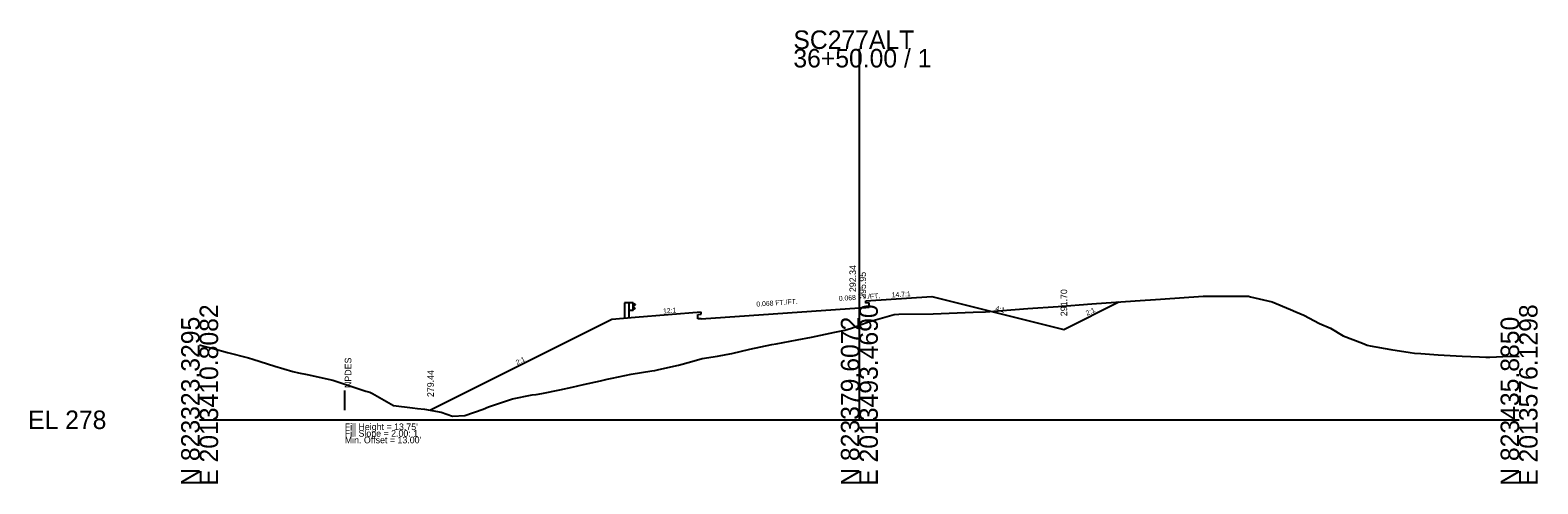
# Model space of a CAD drawing. Extents: x 205929 to 2357175, y -1785700 to 827636.
# Drawn here: x 2018394.5 to 2018623, y 824534.6 to 824603.3 of the extents above; entities that cross this region are included whole.
import ezdxf

# ---------------------------------------------------------------- set-up
doc = ezdxf.new("R2010")
doc.units = 0
for name, color, linetype in [('RD_GPK_XS_Cell', 7, 'Continuous'), ('RD_XS_Base', 7, 'Continuous'), ('RD_XS_EarthShd', 7, 'Continuous'), ('RD_XS_ExGround', 7, 'Continuous'), ('RD_XS_GR', 7, 'Continuous'), ('RD_XS_NPDES', 7, 'Continuous'), ('RD_XS_Pave', 7, 'Continuous'), ('RD_XS_TieSlope', 7, 'Continuous'), ('RD_XS_TX_Elev_EX', 7, 'Continuous'), ('RD_XS_TX_Elev_PR', 7, 'Continuous'), ('RD_XS_TX_ShdSlope', 7, 'Continuous'), ('RD_XS_TX_Slope', 7, 'Continuous'), ('RD_XS_TX_Warning', 7, 'Continuous')]:
    doc.layers.add(name, color=color, linetype=linetype)

msp = doc.modelspace()

# ---------------------------------------------------------------- linework, layer by layer
at = {"layer": 'RD_GPK_XS_Cell'}
for p, q in [((2018520.17, 824544.26), (2018520.17, 824600.42)), ((2018420.17, 824544.26), (2018520.17, 824544.26)), ((2018520.17, 824544.26), (2018620.17, 824544.26))]:
    msp.add_line(p, q, dxfattribs=at)
at = {"layer": 'RD_XS_Base'}
for p, q in [((2018496.17, 824559.57), (2018520.17, 824561.2)), ((2018520.17, 824561.2), (2018521.17, 824561.27))]:
    msp.add_line(p, q, dxfattribs=at)
at = {"layer": 'RD_XS_EarthShd'}
for p, q in [((2018521.17, 824562.27), (2018531.17, 824562.95)), ((2018486.17, 824559.74), (2018482.67, 824559.45)), ((2018496.17, 824560.57), (2018486.17, 824559.74))]:
    msp.add_line(p, q, dxfattribs=at)
at = {"layer": 'RD_XS_ExGround'}
msp.add_lwpolyline([(2018420.17, 824555.59), (2018420.79, 824555.42), (2018422.2, 824555.04), (2018424.38, 824554.45), (2018427.6, 824553.63), (2018428.24, 824553.46), (2018431.58, 824552.37), (2018434.29, 824551.58), (2018435.18, 824551.35), (2018436.49, 824551.11), (2018440.34, 824550.27), (2018445.37, 824548.6), (2018445.98, 824548.42), (2018446.39, 824548.25), (2018449.58, 824546.42), (2018452.44, 824546.07), (2018453.17, 824545.96), (2018454.25, 824545.86), (2018456.77, 824545.41), (2018458.49, 824544.83), (2018460.37, 824544.9), (2018463.14, 824545.89), (2018463.97, 824546.22), (2018464.54, 824546.4), (2018467.57, 824547.43), (2018470.59, 824548.03), (2018471.17, 824548.09), (2018472.02, 824548.25), (2018474.77, 824548.8), (2018476.63, 824549.21), (2018478.37, 824549.6), (2018480.91, 824550.16), (2018481.96, 824550.4), (2018482.68, 824550.56), (2018485.56, 824551.17), (2018488.73, 824551.65), (2018489.16, 824551.74), (2018489.79, 824551.88), (2018492.76, 824552.53), (2018494.78, 824553.08), (2018496.36, 824553.52), (2018498.68, 824553.91), (2018499.96, 824554.17), (2018500.83, 824554.3), (2018503.56, 824554.97), (2018506.88, 824555.64), (2018507.56, 824555.76), (2018510.75, 824556.35), (2018512.93, 824556.78), (2018514.35, 824557.08), (2018516.45, 824557.51), (2018517.95, 824557.82), (2018518.98, 824558.16), (2018520.17, 824558.6), (2018521.55, 824559.1), (2018525.44, 824560.23), (2018526.17, 824560.24), (2018531.36, 824560.29), (2018537.43, 824560.55), (2018539.29, 824560.63), (2018545.7, 824561.1), (2018550.28, 824561.44), (2018555.43, 824561.82), (2018561.95, 824562.29), (2018565.84, 824562.54), (2018572.29, 824562.97), (2018576.78, 824562.97), (2018577.93, 824562.98), (2018578.33, 824562.98), (2018579.13, 824562.97), (2018579.46, 824562.9), (2018582.73, 824562.11), (2018585.51, 824560.98), (2018586.33, 824560.62), (2018587.52, 824560.08), (2018589.93, 824558.86), (2018591.56, 824558.12), (2018593.52, 824556.95), (2018596.41, 824555.86), (2018597.12, 824555.55), (2018597.61, 824555.46), (2018600.72, 824554.88), (2018603.66, 824554.47), (2018604.32, 824554.34), (2018605.29, 824554.28), (2018607.92, 824554.08), (2018609.71, 824554), (2018611.52, 824553.89), (2018614.18, 824553.78), (2018615.12, 824553.74), (2018615.76, 824553.76), (2018618.72, 824553.87), (2018620.17, 824553.83)], dxfattribs=at)
at = {"layer": 'RD_XS_GR'}
for p, q in [((2018484.57, 824561.99), (2018484.57, 824559.61)), ((2018485.24, 824561.99), (2018484.57, 824561.99)), ((2018485.24, 824561.99), (2018485.24, 824559.66)), ((2018485.9, 824561.99), (2018485.24, 824561.99)), ((2018485.9, 824560.82), (2018485.9, 824561.99)), ((2018485.9, 824561.92), (2018486.17, 824561.72)), ((2018486.17, 824561.67), (2018485.9, 824561.47)), ((2018486.17, 824561.72), (2018486.17, 824561.67)), ((2018485.9, 824560.82), (2018485.24, 824560.82)), ((2018486.17, 824561.15), (2018485.9, 824561.35)), ((2018485.9, 824560.9), (2018486.17, 824561.1)), ((2018486.17, 824561.1), (2018486.17, 824561.15))]:
    msp.add_line(p, q, dxfattribs=at)
at = {"layer": 'RD_XS_NPDES'}
msp.add_line((2018442.17, 824545.7), (2018442.17, 824548.7), dxfattribs=at)
at = {"layer": 'RD_XS_Pave'}
for p, q in [((2018521.17, 824561.94), (2018521.17, 824562.27)), ((2018521.67, 824561.98), (2018521.17, 824561.94)), ((2018521.67, 824561.31), (2018521.67, 824561.98)), ((2018495.67, 824560.21), (2018496.17, 824560.24)), ((2018495.67, 824559.54), (2018495.67, 824560.21)), ((2018496.17, 824559.57), (2018495.67, 824559.54)), ((2018496.17, 824560.24), (2018496.17, 824560.57)), ((2018521.17, 824561.27), (2018521.67, 824561.31))]:
    msp.add_line(p, q, dxfattribs=at)
at = {"layer": 'RD_XS_TieSlope'}
for p, q in [((2018531.17, 824562.95), (2018551.17, 824557.95)), ((2018551.17, 824557.95), (2018559.49, 824562.11)), ((2018482.67, 824559.45), (2018455.17, 824545.7))]:
    msp.add_line(p, q, dxfattribs=at)

# ---------------------------------------------------------------- texts
at = {"layer": 'RD_GPK_XS_Cell'}
for s, p in [('SC277ALT', (2018510.17, 824600.42)), ('36+50.00 / 1', (2018510.17, 824597.62)), ('EL 278', (2018394.17, 824542.86))]:
    msp.add_text(s, height=2.8, dxfattribs=at).set_placement(p)
for s, p in [('N 823323.3295', (2018420.17, 824534.26)), ('E 2013410.8082', (2018422.97, 824534.26)), ('N 823379.6072', (2018520.17, 824534.26)), ('E 2013493.4690', (2018522.97, 824534.26)), ('N 823435.8850', (2018620.17, 824534.26)), ('E 2013576.1298', (2018622.97, 824534.26))]:
    msp.add_text(s, height=2.8, rotation=90, dxfattribs=at).set_placement(p)
at = {"layer": 'RD_XS_TX_Elev_EX'}
msp.add_text('292.34', height=1, rotation=90, dxfattribs=at).set_placement((2018519.67, 824563.6))
at = {"layer": 'RD_XS_TX_Elev_PR'}
for s, p in [(' 295.95', (2018521.17, 824562.2)), ('291.70', (2018551.67, 824559.95)), ('279.44', (2018455.67, 824547.7))]:
    msp.add_text(s, height=1, rotation=90, dxfattribs=at).set_placement(p)
at = {"layer": 'RD_XS_TX_ShdSlope'}
for s, rotation, p in [('14.7:1', 3.8884, (2018525.1, 824562.79)), ('12:1', 4.7636, (2018490.44, 824560.35))]:
    msp.add_text(s, height=0.75, rotation=rotation, dxfattribs=at).set_placement(p)
at = {"layer": 'RD_XS_TX_Slope'}
for s, rotation, p in [('0.068 FT./FT.', 3.8884, (2018504.58, 824561.4)), ('0.068 FT./FT.', 3.8884, (2018517.08, 824562.25)), ('4:1', 345.9638, (2018540.72, 824560.82)), ('2:1', 26.5651, (2018554.71, 824560)), ('2:1', 26.5651, (2018468.31, 824552.54))]:
    msp.add_text(s, height=0.75, rotation=rotation, dxfattribs=at).set_placement(p)
at = {"layer": 'RD_XS_TX_Warning'}
msp.add_text(' NPDES', height=1, rotation=90, dxfattribs=at).set_placement((2018443.17, 824548.7))
for s, p in [("Fill Height = 13.75' ", (2018442.17, 824542.7)), ('Fill Slope = 2.00: 1', (2018442.17, 824541.7)), ("Min. Offset = 13.00' ", (2018442.17, 824540.7))]:
    msp.add_text(s, height=1, dxfattribs=at).set_placement(p)

doc.saveas('drawing.dxf')
